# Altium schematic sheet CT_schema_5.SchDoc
size 522 x 483 mm
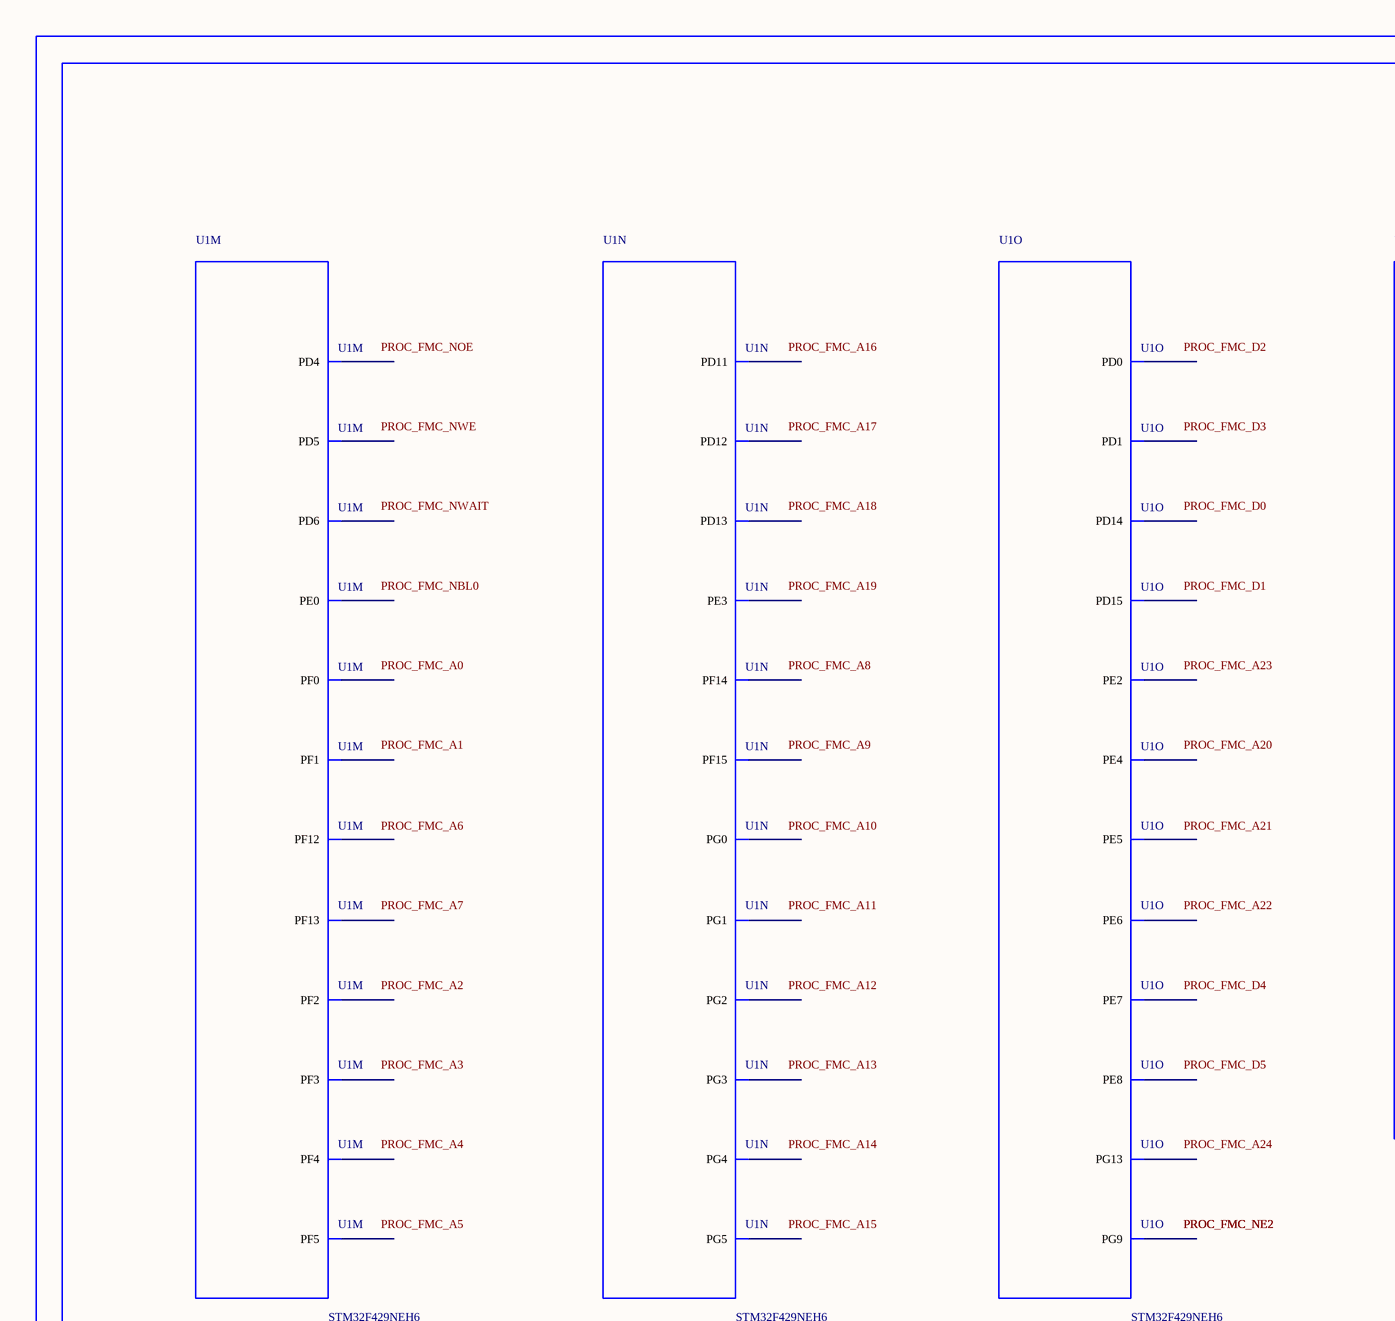
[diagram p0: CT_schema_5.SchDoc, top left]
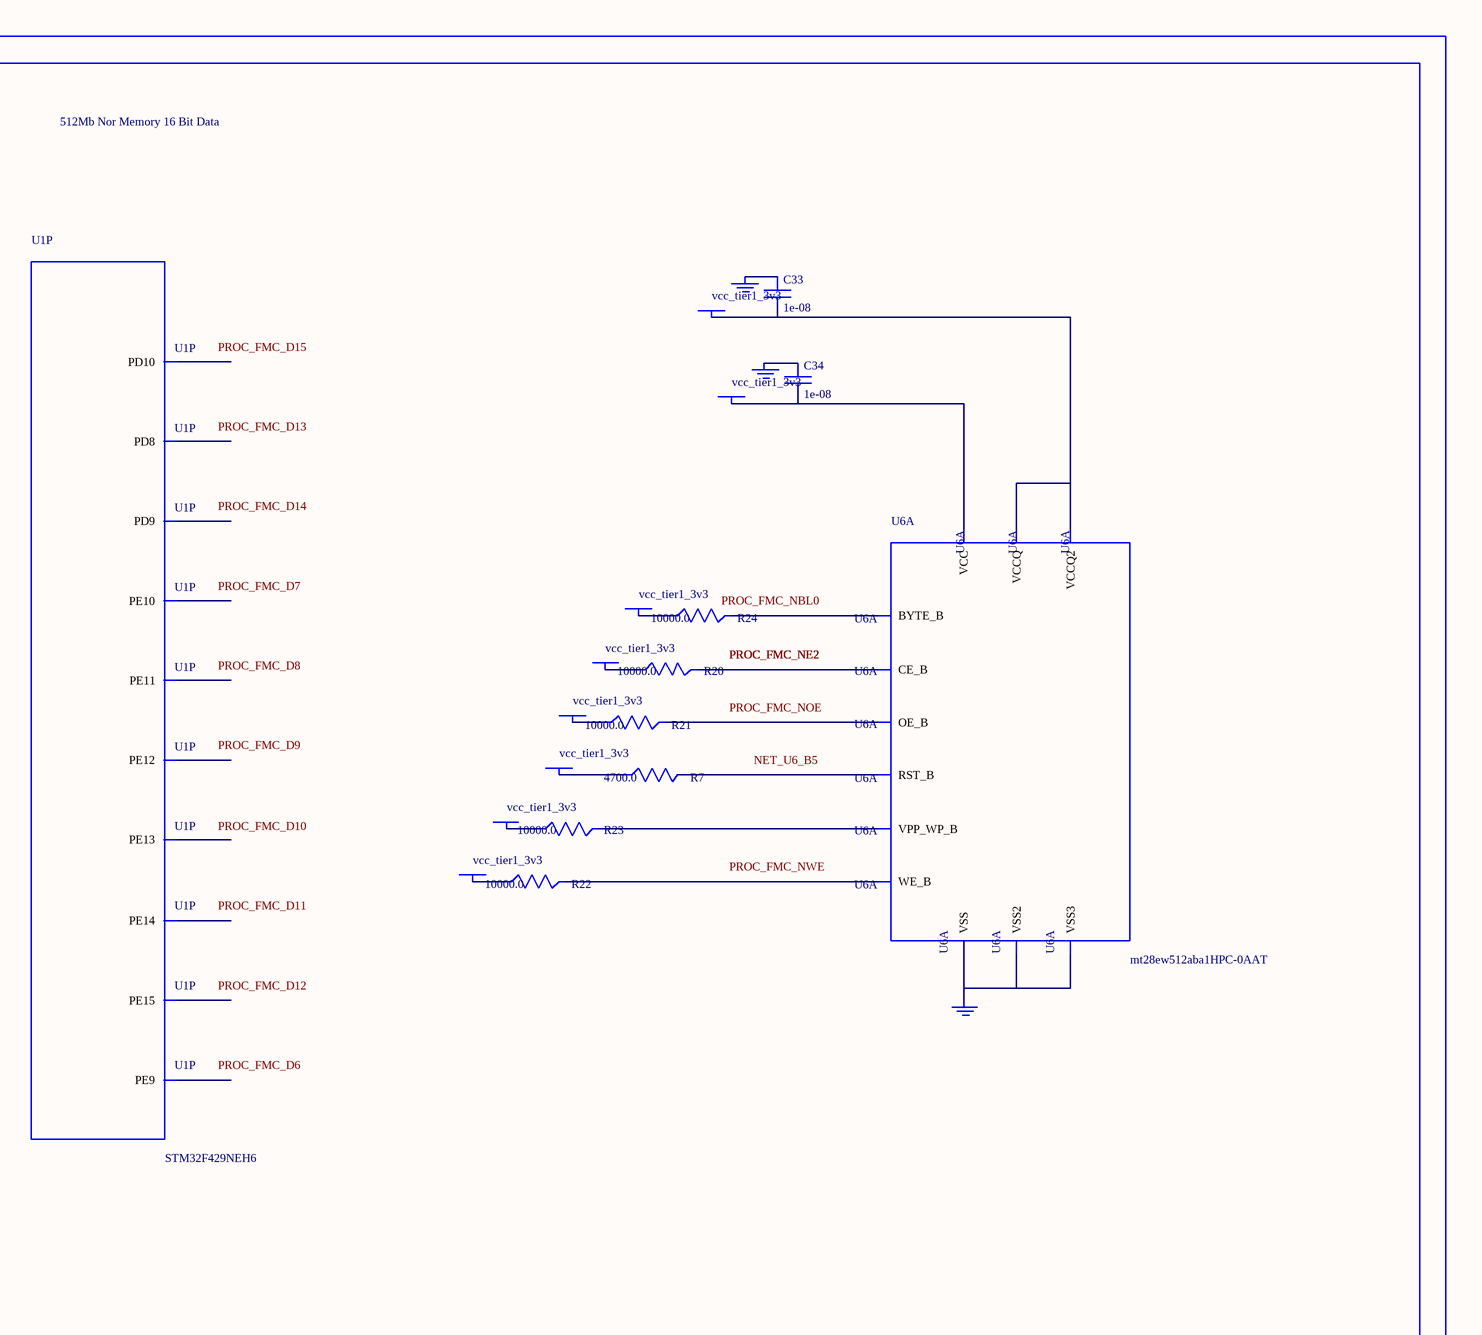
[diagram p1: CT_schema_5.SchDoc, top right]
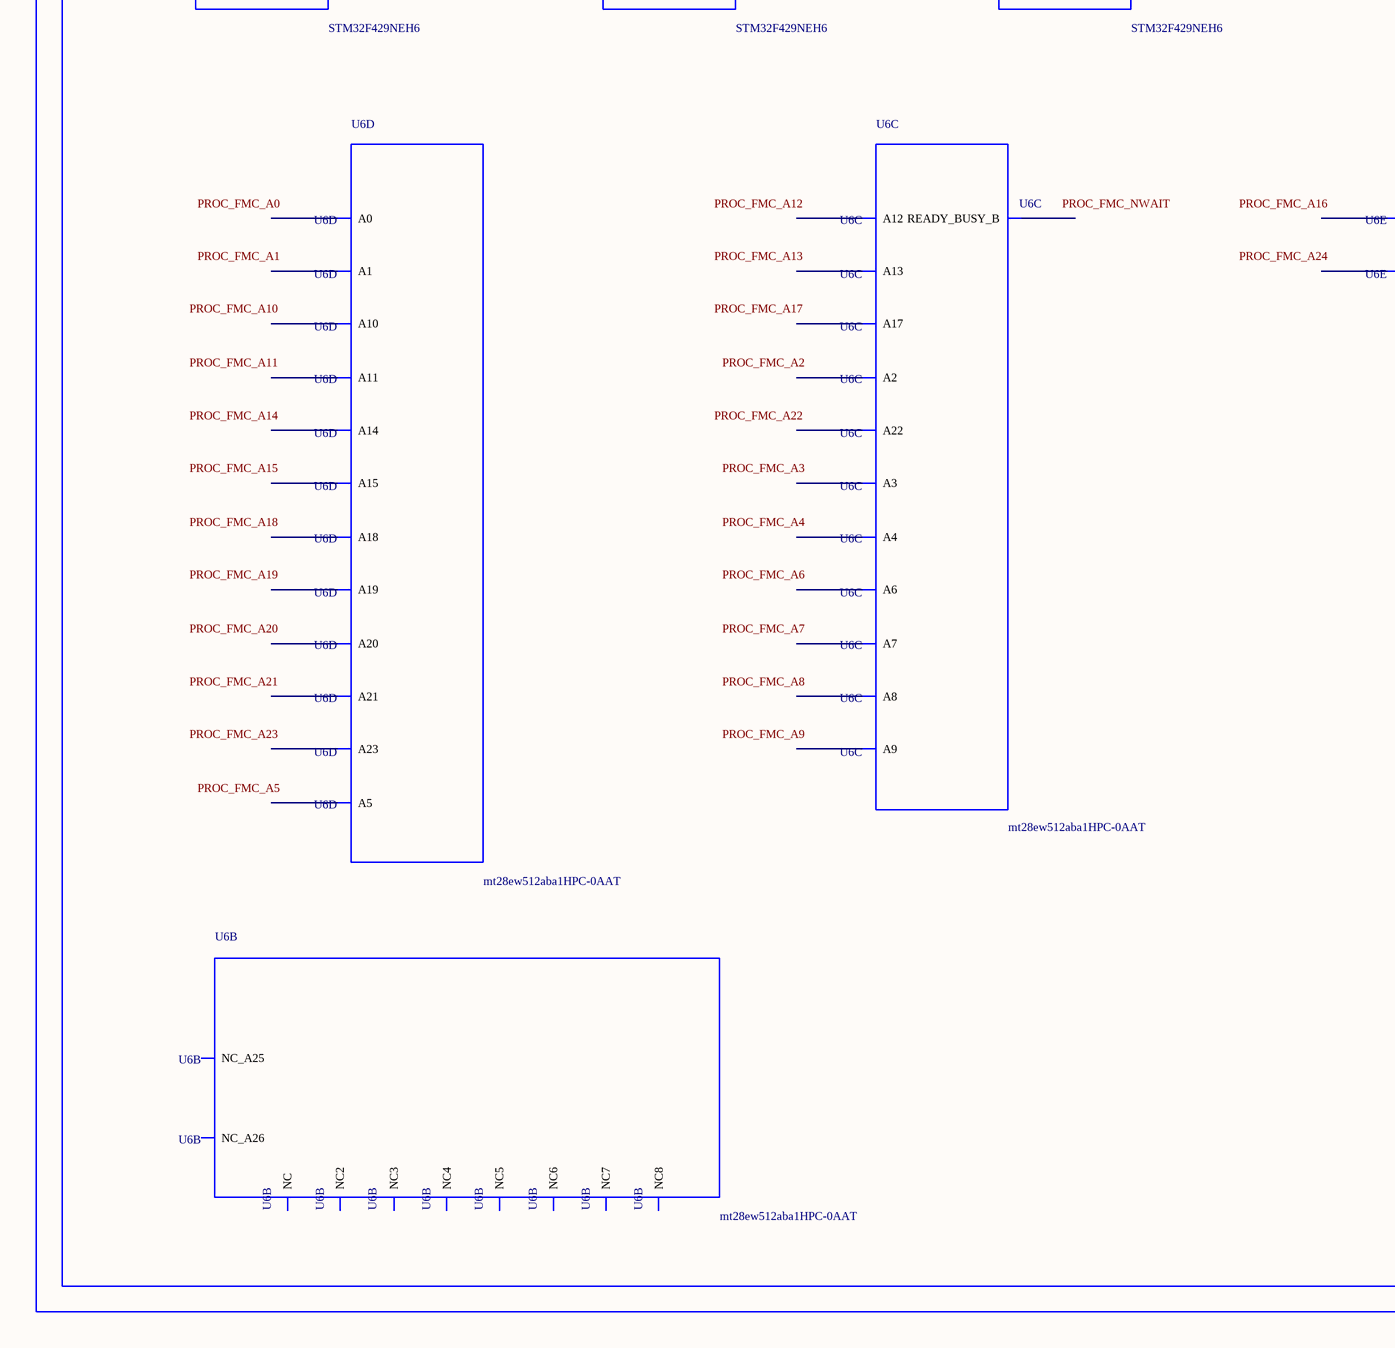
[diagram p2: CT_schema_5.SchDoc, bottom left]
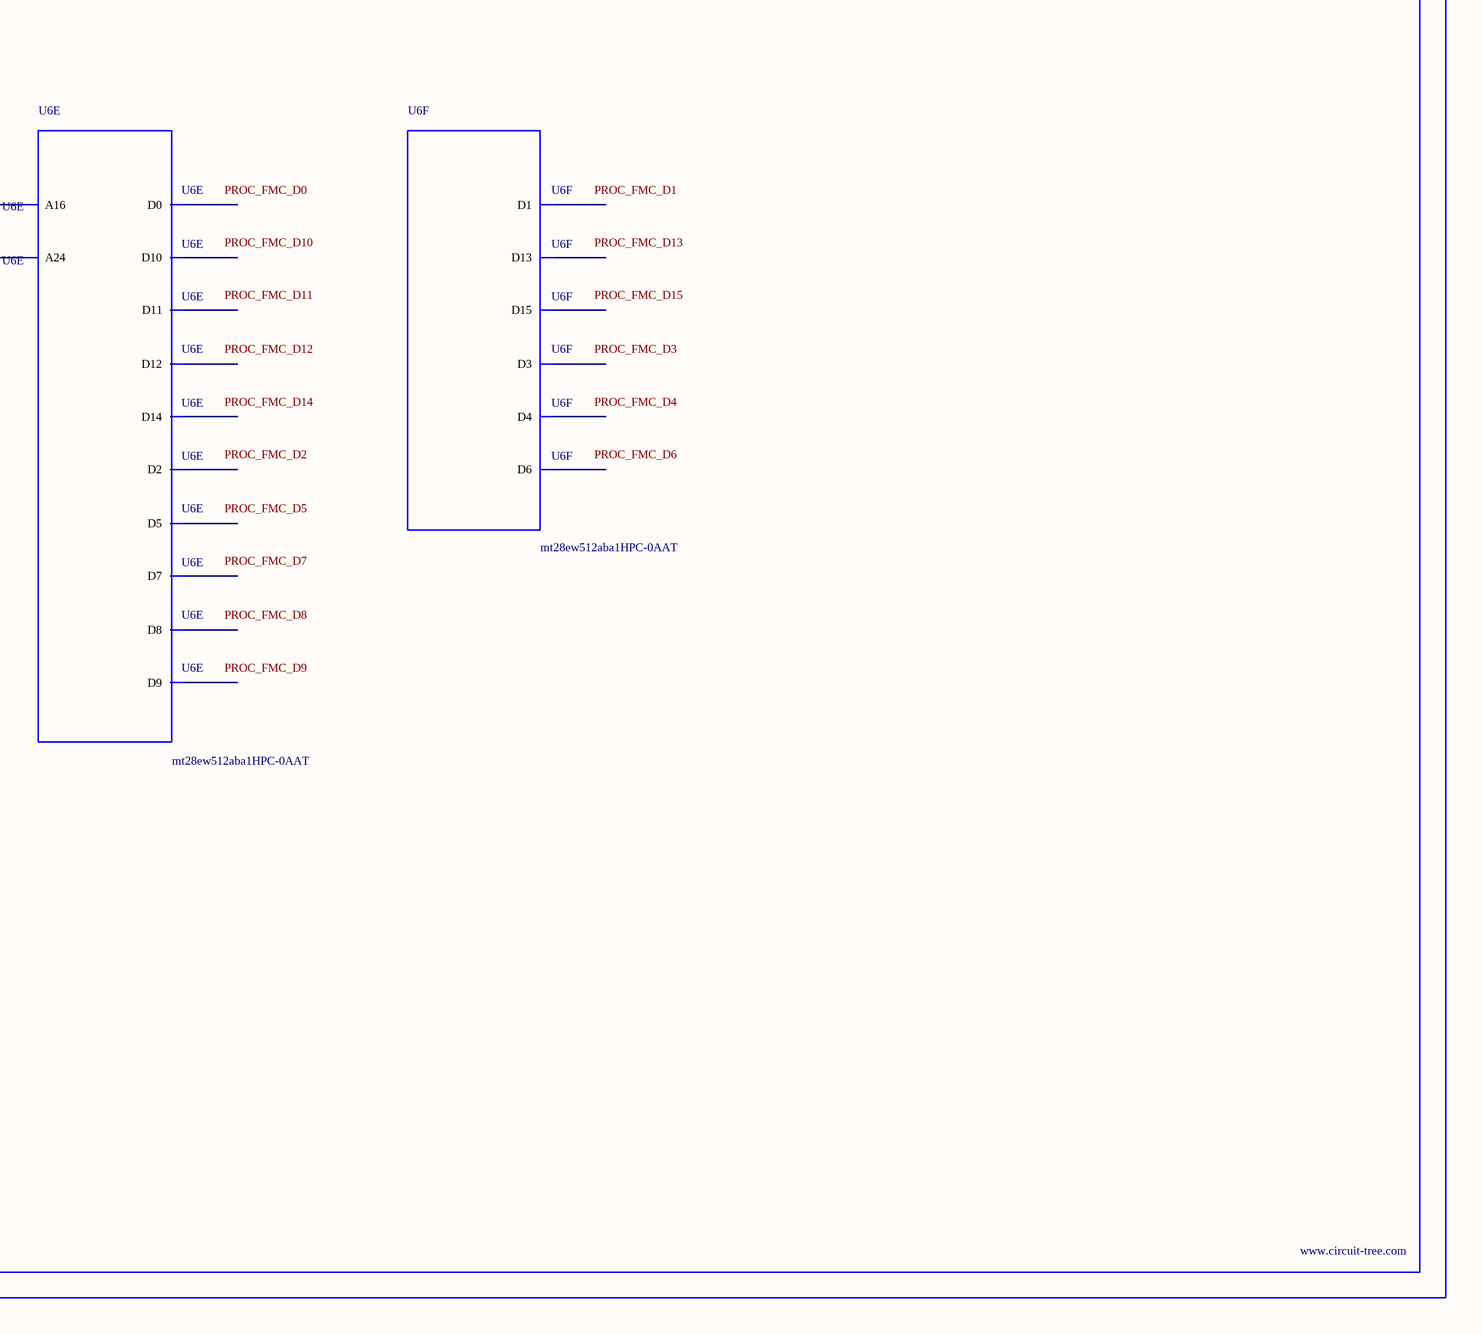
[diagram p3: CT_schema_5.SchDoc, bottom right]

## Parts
BORDER4  (no value)
C33  1e-08  [C0402]
C34  1e-08  [C0402]
GND_INSTANCE_4_0  (no value)
GND_INSTANCE_4_1  (no value)
GND_INSTANCE_4_2  (no value)
POWER_INSTANCE_4_0  vcc_tier1_3v3
POWER_INSTANCE_4_1  vcc_tier1_3v3
POWER_INSTANCE_4_2  vcc_tier1_3v3
POWER_INSTANCE_4_3  vcc_tier1_3v3
POWER_INSTANCE_4_4  vcc_tier1_3v3
POWER_INSTANCE_4_5  vcc_tier1_3v3
POWER_INSTANCE_4_6  vcc_tier1_3v3
POWER_INSTANCE_4_7  vcc_tier1_3v3
R7  4700.0  [R0603]
R20  10000.0  [R0603]
R21  10000.0  [R0603]
R22  10000.0  [R0603]
R23  10000.0  [R0603]
R24  10000.0  [R0603]
U1  STM32F429NEH6  [TFBGA216]  (parts M,N,O,P of 17)
U6  mt28ew512aba1HPC-0AAT  [LBGA-64]  (parts A,B,C,D,E,F of 6)

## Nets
NetC33_1: C33.1 GND_INSTANCE_4_0.0(GND)
NetC33_2: C33.2 POWER_INSTANCE_4_0.0(PWR) U6.D8(VCCQ) U6.F1(VCCQ2)
NetC34_1: C34.1 GND_INSTANCE_4_1.0(GND)
NetC34_2: C34.2 POWER_INSTANCE_4_1.0(PWR) U6.G5(VCC)
NetGND_INSTANCE_4_2_0: GND_INSTANCE_4_2.0(GND) U6.E8(VSS) U6.H2(VSS2) U6.H7(VSS3)
NetPOWER_INSTANCE_4_2_0: POWER_INSTANCE_4_2.0(PWR) R20.1
NetPOWER_INSTANCE_4_3_0: POWER_INSTANCE_4_3.0(PWR) R21.1
NetPOWER_INSTANCE_4_4_0: POWER_INSTANCE_4_4.0(PWR) R22.1
NetPOWER_INSTANCE_4_5_0: POWER_INSTANCE_4_5.0(PWR) R23.1
NetPOWER_INSTANCE_4_6_0: POWER_INSTANCE_4_6.0(PWR) R24.1
NetPOWER_INSTANCE_4_7_0: POWER_INSTANCE_4_7.0(PWR) R7.1
NetR7_2: R7.2 U6.B5(RST_B)
NetR20_2: R20.2 U6.F2(CE_B)
NetR21_2: R21.2 U6.G2(OE_B)
NetR22_2: R22.2 U6.A5(WE_B)
NetR23_2: R23.2 U6.B4(VPP_WP_B)
NetR24_2: R24.2 U6.F7(BYTE_B)

Not connected (* = marked no-connect by the designer): U1 A1(PE4) A2(PE3) A3(PE2) A6(PE0) B1(PE5) B2(PE6) B3(PG13) B11(PD6) B12(PD0) C10(PD5) C12(PD1) D2(PF0) D9(PG9) D11(PD4) E2(PF1) G2(PF2) H2(PF3) J2(PF4) K3(PF5) K13(PD15) K15(PD10) L12(PD14) L14(PD9) L15(PD8) M6(PF12) M7(PG1) M8(PF15) M10(PD12) M11(PD13) M12(PG3) M13(PG2) N6(PF13) N7(PG0) N9(PE8) N10(PD11) N11(PG5) N12(PG4) P6(PF14) P9(PE9) P10(PE11) P11(PE14) R8(PE7) R9(PE10) R10(PE12) R11(PE15) R12(PE13); U6 A1(NC) A2(A3) A3(A7) A4(READY_BUSY_B) A6(A9) A7(A13) A8(NC2) B1(NC_A26) B2(A4) B3(A17) B6(A8) B7(A12) B8(A22) C1(NC3) C2(A2) C3(A6) C4(A18) C5(A21) C6(A10) C7(A14) C8(A23) D1(NC4) D2(A1) D3(A5) D4(A20) D5(A19) D6(A11) D7(A15) E1(NC5) E2(A0) E3(D0) E4(D2) E5(D5) E6(D7) E7(A16) F3(D8) F4(D10) F5(D12) F6(D14) F8(A24) G1(NC6) G3(D9) G4(D11) G6(D13) G7(D15) G8(NC_A25) H1(NC7) H3(D1) H4(D3) H5(D4) H6(D6) H8(NC8)

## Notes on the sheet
- Labels drawn without touching a wire or pin: NET_U6_B5, PROC_FMC_A0, PROC_FMC_A1, PROC_FMC_A2, PROC_FMC_A3, PROC_FMC_A4, PROC_FMC_A5, PROC_FMC_A6, PROC_FMC_A7, PROC_FMC_A8, PROC_FMC_A9, PROC_FMC_A10, PROC_FMC_A11, PROC_FMC_A12, PROC_FMC_A13, PROC_FMC_A14, PROC_FMC_A15, PROC_FMC_A16, PROC_FMC_A17, PROC_FMC_A18, PROC_FMC_A19, PROC_FMC_A20, PROC_FMC_A21, PROC_FMC_A22, PROC_FMC_A23, PROC_FMC_A24, PROC_FMC_D0, PROC_FMC_D1, PROC_FMC_D2, PROC_FMC_D3, PROC_FMC_D4, PROC_FMC_D5, PROC_FMC_D6, PROC_FMC_D7, PROC_FMC_D8, PROC_FMC_D9, PROC_FMC_D10, PROC_FMC_D11, PROC_FMC_D12, PROC_FMC_D13, PROC_FMC_D14, PROC_FMC_D15, PROC_FMC_NBL0, PROC_FMC_NOE, PROC_FMC_NWAIT, PROC_FMC_NWE

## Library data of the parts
BORDER4 = BORDER_PAGE4
C33 C34 = C0402C103K3RAC
GND_INSTANCE_4_0-GND_INSTANCE_4_2 = GND
POWER_INSTANCE_4_0-POWER_INSTANCE_4_7 = PWR
R7 = RC0603JR-074K7L
R20-R24 = RC0603JR-0710KL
